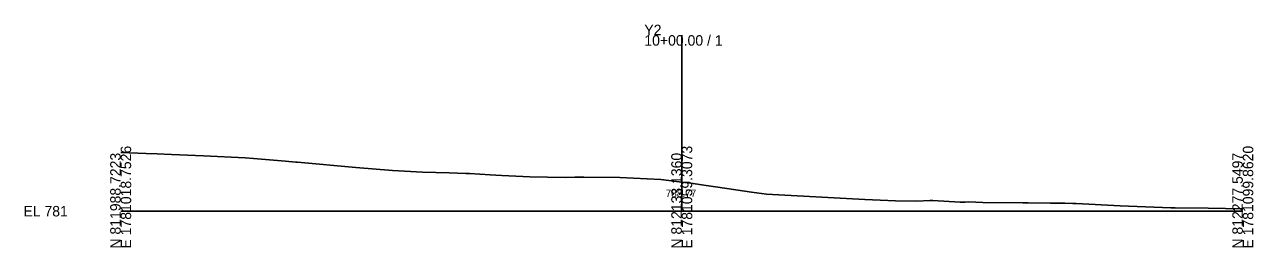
# Model space of a CAD drawing. Extents: x -26 to 303, y -10 to 3096.
# Drawn here: x -25.7 to 302.8, y -9.7 to 49.9 of the extents above; entities that cross this region are included whole.
import ezdxf

# ---------------------------------------------------------------- set-up
doc = ezdxf.new("R2010")
doc.units = 0
for name, color, linetype in [('Exist Cross Section Cell', 7, 'Continuous'), ('Exist XS Center Line Elevation Label', 7, 'Continuous'), ('Exist XS Ground Line', 7, 'Continuous')]:
    doc.layers.add(name, color=color, linetype=linetype)

msp = doc.modelspace()

# ---------------------------------------------------------------- linework, layer by layer
at = {"layer": 'Exist Cross Section Cell'}
for p, q in [((150, 0), (150, 47.06)), ((0, 0), (150, 0)), ((150, 0), (300, 0))]:
    msp.add_line(p, q, dxfattribs=at)
at = {"layer": 'Exist XS Ground Line'}
for p, q in [((0, 15.69), (6.77, 15.43)), ((6.77, 15.43), (9.78, 15.35)), ((9.78, 15.35), (13.55, 15.18)), ((13.55, 15.18), (22.14, 14.84)), ((22.14, 14.84), (33.25, 14.24)), ((33.25, 14.24), (35.52, 14.11)), ((35.52, 14.11), (44.08, 13.37)), ((44.08, 13.37), (46.8, 13.14)), ((46.8, 13.14), (47.25, 13.1)), ((47.25, 13.1), (62.9, 11.71)), ((62.9, 11.71), (72.7, 10.89)), ((72.7, 10.89), (77.47, 10.58)), ((77.47, 10.58), (80.72, 10.41)), ((80.72, 10.41), (87.85, 10.22)), ((87.85, 10.22), (92.27, 10.09)), ((92.27, 10.09), (93.27, 10.04)), ((93.27, 10.04), (98.8, 9.76)), ((98.8, 9.76), (100.31, 9.59)), ((100.31, 9.59), (101.86, 9.51)), ((101.86, 9.51), (109.35, 9.14)), ((109.35, 9.14), (118.87, 9.03)), ((118.87, 9.03), (121.45, 9.08)), ((121.45, 9.08), (123.83, 9.12)), ((123.83, 9.12), (133.41, 9.04)), ((133.41, 9.04), (144.37, 8.44)), ((144.37, 8.44), (150, 7.77)), ((150, 7.77), (153.05, 7.41)), ((153.05, 7.41), (155.94, 6.96)), ((155.94, 6.96), (159.66, 6.42)), ((159.66, 6.42), (168.64, 5.08)), ((168.64, 5.08), (172.69, 4.59)), ((172.69, 4.59), (198.98, 3.12)), ((198.98, 3.12), (207.13, 2.76)), ((207.13, 2.76), (212.84, 2.69)), ((212.84, 2.69), (216.34, 2.86)), ((216.34, 2.86), (217.12, 2.88)), ((217.12, 2.88), (224.47, 2.4)), ((224.47, 2.4), (225.81, 2.43)), ((225.81, 2.43), (226.71, 2.46)), ((226.71, 2.46), (230.51, 2.31)), ((230.51, 2.31), (241.18, 2.27)), ((241.18, 2.27), (242.65, 2.27)), ((242.65, 2.27), (248.59, 2.15)), ((248.59, 2.15), (249.87, 2.14)), ((249.87, 2.14), (252.44, 2.1)), ((252.44, 2.1), (254.57, 2.08)), ((254.57, 2.08), (255.49, 2.07)), ((255.49, 2.07), (267.22, 1.47)), ((267.22, 1.47), (280.72, 0.93)), ((280.72, 0.93), (281.93, 0.9)), ((281.93, 0.9), (290.71, 0.84)), ((290.71, 0.84), (300, 0.62))]:
    msp.add_line(p, q, dxfattribs=at)

# ---------------------------------------------------------------- texts
at = {"layer": 'Exist Cross Section Cell'}
for s, p in [('Y2', (140, 47.06)), ('10+00.00 / 1', (140, 44.26)), ('EL 781', (-26, -1.4))]:
    msp.add_text(s, height=2.8, dxfattribs=at).set_placement(p)
for s, p in [('E 1781018.7526', (2.8, -10)), ('E 1781059.3073', (152.8, -10)), ('E 1781099.8620', (302.8, -10)), ('N 811988.7223', (0, -10)), ('N 812133.1360', (150, -10)), ('N 812277.5497', (300, -10))]:
    msp.add_text(s, height=2.8, rotation=90, dxfattribs=at).set_placement(p)
at = {"layer": 'Exist XS Center Line Elevation Label'}
msp.add_text('788.77', height=2, dxfattribs=at).set_placement((145.7, 3.77))

doc.saveas('drawing.dxf')
